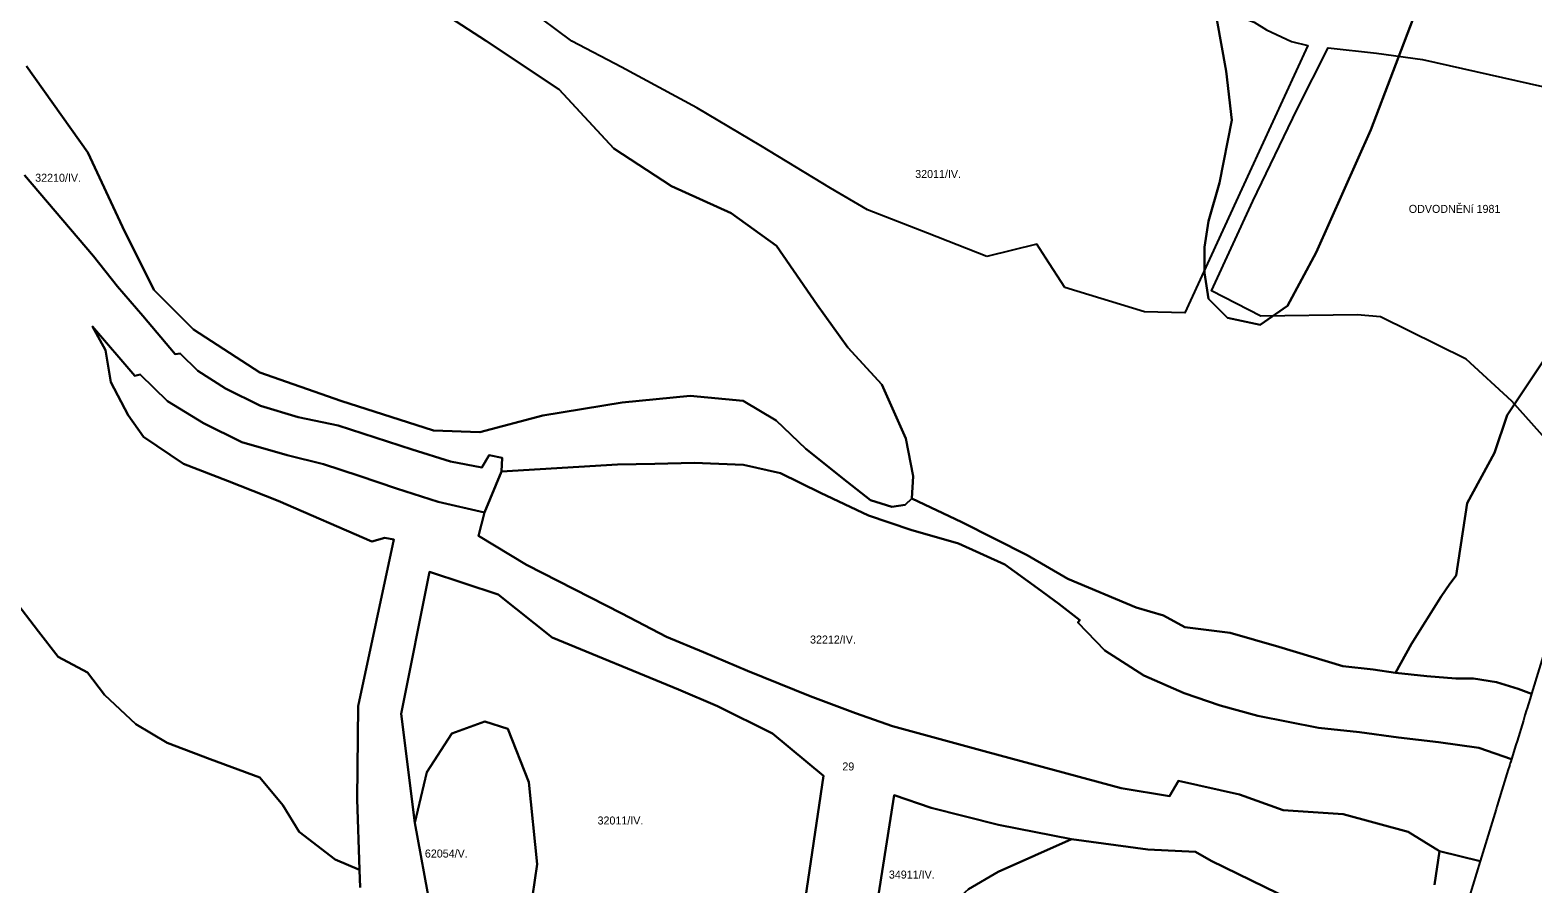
# Model space of a CAD drawing. Extents: x -521621 to -516761, y -1190184 to -1184927.
# Drawn here: x -518211 to -517460, y -1188092 to -1187665 of the extents above; entities that cross this region are included whole.
import ezdxf

# ---------------------------------------------------------------- set-up
doc = ezdxf.new("R2010")
doc.units = 0
doc.layers.add('BPEJ_s', color=7, linetype='Continuous')
doc.layers.add('odvodneni_s', color=7, linetype='Continuous')

msp = doc.modelspace()

# ---------------------------------------------------------------- linework, layer by layer
at = {"layer": 'BPEJ_s'}
for p, q in [((-518213.64, -1187737.85), (-518179.13, -1187778.41)), ((-518179.13, -1187778.41), (-518167.09, -1187793.48)), ((-518167.09, -1187793.48), (-518154.41, -1187808.16)), ((-518154.41, -1187808.16), (-518138.39, -1187827.34)), ((-518158.47, -1187838.17), (-518179.66, -1187813.57)), ((-518179.66, -1187813.57), (-518173.12, -1187825.31)), ((-518173.12, -1187825.31), (-518170.41, -1187841.33)), ((-518138.39, -1187827.34), (-518135.81, -1187827.06)), ((-518135.81, -1187827.06), (-518126.94, -1187835.65)), ((-518155.76, -1187837.49), (-518158.47, -1187838.17)), ((-518142.23, -1187850.8), (-518155.76, -1187837.49)), ((-518126.94, -1187835.65), (-518113.21, -1187844.53)), ((-518170.41, -1187841.33), (-518161.85, -1187857.8)), ((-518113.21, -1187844.53), (-518095.75, -1187853.12)), ((-518124.19, -1187861.86), (-518142.23, -1187850.8)), ((-518095.75, -1187853.12), (-518076.87, -1187858.85)), ((-518161.85, -1187857.8), (-518154.18, -1187868.63)), ((-518076.87, -1187858.85), (-518056.84, -1187863)), ((-518154.18, -1187868.63), (-518134.11, -1187882.17)), ((-518105.03, -1187871.34), (-518124.19, -1187861.86)), ((-518056.84, -1187863), (-518019.92, -1187875.03)), ((-518082.26, -1187877.88), (-518105.03, -1187871.34)), ((-518019.92, -1187875.03), (-518000.61, -1187881.04)), ((-518134.11, -1187882.17), (-518112.24, -1187890.75)), ((-518064.22, -1187882.4), (-518082.26, -1187877.88)), ((-518046.39, -1187888.2), (-518064.22, -1187882.4)), ((-518000.61, -1187881.04), (-517985.01, -1187884.05)), ((-517985.01, -1187884.05), (-517981.29, -1187877.89)), ((-517981.29, -1187877.89), (-517974.85, -1187879.18)), ((-517974.85, -1187879.18), (-517975.14, -1187886.06)), ((-518112.24, -1187890.75), (-518086.88, -1187900.67)), ((-518027.65, -1187894.51), (-518046.39, -1187888.2)), ((-517975.14, -1187886.06), (-517983.72, -1187906.53)), ((-518006.9, -1187901.24), (-518027.65, -1187894.51)), ((-518086.88, -1187900.67), (-518039.99, -1187921.04)), ((-517983.72, -1187906.53), (-518006.9, -1187901.24)), ((-518029.09, -1187919.95), (-518046.87, -1188003.31)), ((-518039.99, -1187921.04), (-518033.45, -1187919.22)), ((-518033.45, -1187919.22), (-518029.09, -1187919.95)), ((-518206.66, -1187966.08), (-518219.21, -1187949.69)), ((-518196.87, -1187978.64), (-518206.66, -1187966.08)), ((-518182.2, -1187986.52), (-518196.87, -1187978.64)), ((-518173.59, -1187997.71), (-518182.2, -1187986.52)), ((-518157.98, -1188012.41), (-518173.59, -1187997.71)), ((-518046.87, -1188003.31), (-518047.36, -1188049.86)), ((-518142.37, -1188021.59), (-518157.98, -1188012.41)), ((-518120.8, -1188029.86), (-518142.37, -1188021.59)), ((-518096.01, -1188039.05), (-518120.8, -1188029.86)), ((-518084.53, -1188052.83), (-518096.01, -1188039.05)), ((-518076.27, -1188066.15), (-518084.53, -1188052.83)), ((-518047.36, -1188049.86), (-518046.19, -1188085.08)), ((-518058.36, -1188079.93), (-518076.27, -1188066.15)), ((-518046.19, -1188085.08), (-518058.36, -1188079.93))]:
    msp.add_line(p, q, dxfattribs=at)
for points in [[(-517617.66, -1187660.01), (-517612.9, -1187685.91), (-517610.17, -1187710.45), (-517616.3, -1187741.8), (-517621.75, -1187760.89), (-517623.8, -1187773.84), (-517623.8, -1187786.79), (-517621.75, -1187799.74), (-517612.22, -1187809.28), (-517595.87, -1187812.69), (-517582.24, -1187803.15), (-517567.94, -1187776.56), (-517540.69, -1187715.22), (-517518.21, -1187656.6)], [(-517518.21, -1187656.6), (-517540.69, -1187715.22), (-517567.94, -1187776.56), (-517582.24, -1187803.15), (-517595.87, -1187812.69), (-517612.22, -1187809.28), (-517621.75, -1187799.74), (-517623.8, -1187786.79), (-517623.8, -1187773.84), (-517621.75, -1187760.89), (-517616.3, -1187741.8), (-517610.17, -1187710.45), (-517612.9, -1187685.91), (-517617.66, -1187660.01)], [(-518000.68, -1187659.17), (-517983.27, -1187670.54), (-517946.33, -1187695.06), (-517918.98, -1187724.56), (-517890.21, -1187743.4), (-517860.37, -1187756.91), (-517837.64, -1187773.26), (-517817.39, -1187802.76), (-517802.11, -1187824.08), (-517785.06, -1187842.57), (-517772.99, -1187869.58), (-517769.43, -1187888.42), (-517770.12, -1187899.48), (-517773.34, -1187902.63), (-517780.01, -1187903.61), (-517790.77, -1187900.3), (-517802.35, -1187891.19), (-517823.03, -1187874.64), (-517837.92, -1187860.57), (-517854.46, -1187850.63), (-517880.93, -1187848.15), (-517914.85, -1187851.46), (-517954.55, -1187858.08), (-517985.99, -1187866.36), (-518009.15, -1187865.53), (-518055.47, -1187850.63), (-518096.01, -1187836.56), (-518129.09, -1187815.04), (-518148.95, -1187795.18), (-518164.66, -1187763.72), (-518182.04, -1187726.48), (-518212.64, -1187683.44)], [(-517448.42, -1187821.9), (-517472.41, -1187857.91), (-517478.78, -1187876.76), (-517492.39, -1187901.92), (-517498, -1187937.94), (-517501.04, -1187942.11), (-517505.43, -1187948.44), (-517520.28, -1187972.09), (-517528.25, -1187986.67), (-517539.52, -1187985.02), (-517554.63, -1187983.37), (-517586.52, -1187973.74), (-517610.98, -1187966.59), (-517633.52, -1187963.84), (-517644.24, -1187958.06), (-517657.98, -1187953.94), (-517692.06, -1187939.64), (-517712.4, -1187927.81), (-517745.11, -1187911.31), (-517770.12, -1187899.48), (-517769.43, -1187888.42), (-517772.99, -1187869.58), (-517785.06, -1187842.57), (-517802.11, -1187824.08), (-517817.39, -1187802.76), (-517837.64, -1187773.26), (-517860.37, -1187756.91), (-517890.21, -1187743.4), (-517918.98, -1187724.56), (-517946.33, -1187695.06), (-517983.27, -1187670.54), (-518000.68, -1187659.17)], [(-518212.64, -1187683.44), (-518182.04, -1187726.48), (-518164.66, -1187763.72), (-518148.95, -1187795.18), (-518129.09, -1187815.04), (-518096.01, -1187836.56), (-518055.47, -1187850.63), (-518009.15, -1187865.53), (-517985.99, -1187866.36), (-517954.55, -1187858.08), (-517914.85, -1187851.46), (-517880.93, -1187848.15), (-517854.46, -1187850.63), (-517837.92, -1187860.57), (-517823.03, -1187874.64), (-517802.35, -1187891.19), (-517790.77, -1187900.3), (-517780.01, -1187903.61), (-517773.34, -1187902.63), (-517770.12, -1187899.48), (-517745.11, -1187911.31), (-517712.4, -1187927.81), (-517692.06, -1187939.64), (-517657.98, -1187953.94), (-517644.24, -1187958.06), (-517633.52, -1187963.84), (-517610.98, -1187966.59), (-517586.52, -1187973.74), (-517554.63, -1187983.37), (-517539.52, -1187985.02), (-517528.25, -1187986.67), (-517512.58, -1187988.32), (-517498.14, -1187989.48), (-517489.25, -1187989.48), (-517477.76, -1187991.33), (-517467.02, -1187994.67), (-517460.27, -1187997.18), (-517460.97, -1187999.46), (-517462.6, -1188004.76), (-517462.68, -1188004.99), (-517462.75, -1188005.22), (-517463.55, -1188007.83), (-517464.35, -1188010.44), (-517467.53, -1188020.76), (-517468.1, -1188022.61), (-517470.32, -1188029.84), (-517486.54, -1188024.11), (-517506.82, -1188021.25), (-517526.82, -1188018.96), (-517546.24, -1188016.39), (-517566.8, -1188014.1), (-517597.08, -1188008.1), (-517615.93, -1188002.96), (-517633.93, -1187996.84), (-517654.1, -1187988.05), (-517673.55, -1187975.47), (-517687.08, -1187961.46), (-517686.13, -1187960.27), (-517696.57, -1187952.2), (-517707.24, -1187944.36), (-517723.51, -1187932.46), (-517746.77, -1187921.95), (-517770.52, -1187915.2), (-517791.77, -1187907.94), (-517815.77, -1187896.68), (-517835.78, -1187886.92), (-517854.28, -1187882.67), (-517878.94, -1187881.73), (-517898.5, -1187882.27), (-517917.15, -1187882.45), (-517975.14, -1187886.06), (-517974.85, -1187879.18), (-517981.29, -1187877.89), (-517985.01, -1187884.05), (-518000.61, -1187881.04), (-518019.92, -1187875.03), (-518056.84, -1187863), (-518076.87, -1187858.85), (-518095.75, -1187853.12), (-518113.21, -1187844.53), (-518126.94, -1187835.65), (-518135.81, -1187827.06), (-518138.39, -1187827.34), (-518154.41, -1187808.16), (-518167.09, -1187793.48), (-518179.13, -1187778.41), (-518213.64, -1187737.85)], [(-518045.9, -1188093.97), (-518046.19, -1188085.08), (-518047.36, -1188049.86), (-518046.87, -1188003.31), (-518029.09, -1187919.95), (-518033.45, -1187919.22), (-518039.99, -1187921.04), (-518086.88, -1187900.67), (-518112.24, -1187890.75), (-518134.11, -1187882.17), (-518154.18, -1187868.63), (-518161.85, -1187857.8), (-518170.41, -1187841.33), (-518173.12, -1187825.31), (-518179.66, -1187813.57), (-518158.47, -1187838.17), (-518155.76, -1187837.49), (-518142.23, -1187850.8), (-518124.19, -1187861.86), (-518105.03, -1187871.34), (-518082.26, -1187877.88), (-518064.22, -1187882.4), (-518046.39, -1187888.2), (-518027.65, -1187894.51), (-518006.9, -1187901.24), (-517983.72, -1187906.53), (-517986.73, -1187918.13), (-517962.73, -1187932.64), (-517915.07, -1187957.04), (-517892.64, -1187968.68), (-517874.24, -1187976.3), (-517852.24, -1187985.62), (-517820.93, -1187998.32), (-517798.3, -1188006.79), (-517779.68, -1188013.35), (-517732.15, -1188026.28), (-517665.49, -1188044.33), (-517641.29, -1188048.36), (-517636.78, -1188040.69), (-517606.22, -1188047.55), (-517584.51, -1188055.27), (-517554.52, -1188057.27), (-517521.96, -1188066.13), (-517506.25, -1188075.85), (-517508.82, -1188092.71)], [(-517444.26, -1187945), (-517460.27, -1187997.18), (-517467.02, -1187994.67), (-517477.76, -1187991.33), (-517489.25, -1187989.48), (-517498.14, -1187989.48), (-517512.58, -1187988.32), (-517528.25, -1187986.67), (-517520.28, -1187972.09), (-517505.43, -1187948.44), (-517501.04, -1187942.11), (-517498, -1187937.94), (-517492.39, -1187901.92), (-517478.78, -1187876.76), (-517472.41, -1187857.91), (-517448.42, -1187821.9)], [(-517960.81, -1188106.35), (-517957.37, -1188082.23), (-517961.5, -1188041.34), (-517972.06, -1188014.7), (-517983.54, -1188011.03), (-518000.06, -1188017), (-518012.46, -1188036.29), (-518018.47, -1188061.62), (-518025.33, -1188007.23), (-518011.13, -1187936.17), (-517976.85, -1187947.44), (-517949.92, -1187969), (-517886.76, -1187994.97), (-517867.17, -1188003.31), (-517839.75, -1188017.03), (-517814.29, -1188038.1), (-517833.89, -1188171.06)], [(-517833.89, -1188171.06), (-517814.29, -1188038.1), (-517839.75, -1188017.03), (-517867.17, -1188003.31), (-517886.76, -1187994.97), (-517949.92, -1187969), (-517976.85, -1187947.44), (-518011.13, -1187936.17), (-518025.33, -1188007.23), (-518018.47, -1188061.62), (-518002.81, -1188146.9)], [(-518219.21, -1187949.69), (-518206.66, -1187966.08), (-518196.87, -1187978.64), (-518182.2, -1187986.52), (-518173.59, -1187997.71), (-518157.98, -1188012.41), (-518142.37, -1188021.59), (-518120.8, -1188029.86), (-518096.01, -1188039.05), (-518084.53, -1188052.83), (-518076.27, -1188066.15), (-518058.36, -1188079.93), (-518046.19, -1188085.08), (-518045.9, -1188093.97)], [(-517580.51, -1188100.15), (-517620.48, -1188080.59), (-517628.22, -1188076.12), (-517652.05, -1188074.93), (-517690.18, -1188069.86), (-517726.82, -1188062.71), (-517760.33, -1188054.17), (-517778.93, -1188047.85), (-517795.95, -1188155.97)], [(-517741.81, -1188094.89), (-517726.97, -1188086.09), (-517690.18, -1188069.86), (-517652.05, -1188074.93), (-517628.22, -1188076.12), (-517620.48, -1188080.59), (-517580.51, -1188100.15)], [(-517508.82, -1188092.71), (-517506.25, -1188075.85), (-517485.94, -1188080.73), (-517500.67, -1188128.84)]]:
    msp.add_lwpolyline(points, dxfattribs=at)
for points in [[(-517983.72, -1187906.53), (-517975.14, -1187886.06), (-517917.15, -1187882.45), (-517898.5, -1187882.27), (-517878.94, -1187881.73), (-517854.28, -1187882.67), (-517835.78, -1187886.92), (-517815.77, -1187896.68), (-517791.77, -1187907.94), (-517770.52, -1187915.2), (-517746.77, -1187921.95), (-517723.51, -1187932.46), (-517707.24, -1187944.36), (-517696.57, -1187952.2), (-517686.13, -1187960.27), (-517687.08, -1187961.46), (-517673.55, -1187975.47), (-517654.1, -1187988.05), (-517633.93, -1187996.84), (-517615.93, -1188002.96), (-517597.08, -1188008.1), (-517566.8, -1188014.1), (-517546.24, -1188016.39), (-517526.82, -1188018.96), (-517506.82, -1188021.25), (-517486.54, -1188024.11), (-517470.32, -1188029.84), (-517470.7, -1188031.07), (-517470.92, -1188031.77), (-517471.13, -1188032.47), (-517471.52, -1188033.71), (-517471.9, -1188034.95), (-517474.43, -1188043.17), (-517476.96, -1188051.38), (-517477.28, -1188052.43), (-517477.6, -1188053.48), (-517477.81, -1188054.16), (-517478.02, -1188054.84), (-517485.94, -1188080.73), (-517506.25, -1188075.85), (-517521.96, -1188066.13), (-517554.52, -1188057.27), (-517584.51, -1188055.27), (-517606.22, -1188047.55), (-517636.78, -1188040.69), (-517641.29, -1188048.36), (-517665.49, -1188044.33), (-517732.15, -1188026.28), (-517779.68, -1188013.35), (-517798.3, -1188006.79), (-517820.93, -1187998.32), (-517852.24, -1187985.62), (-517874.24, -1187976.3), (-517892.64, -1187968.68), (-517915.07, -1187957.04), (-517962.73, -1187932.64), (-517986.73, -1187918.13)], [(-518018.47, -1188061.62), (-518012.46, -1188036.29), (-518000.06, -1188017), (-517983.54, -1188011.03), (-517972.06, -1188014.7), (-517961.5, -1188041.34), (-517957.37, -1188082.23), (-517960.81, -1188106.35), (-517961.5, -1188111.16), (-517967.47, -1188132.29), (-517977.11, -1188146.99), (-517984.45, -1188150.67), (-517994.55, -1188151.13), (-518000.98, -1188147.91), (-518002.81, -1188146.9)], [(-517795.95, -1188155.97), (-517778.93, -1188047.85), (-517760.33, -1188054.17), (-517726.82, -1188062.71), (-517690.18, -1188069.86), (-517726.97, -1188086.09), (-517741.81, -1188094.89), (-517747.31, -1188099.84), (-517769.3, -1188122.39), (-517781.39, -1188140.55)]]:
    msp.add_lwpolyline(points, close=True, dxfattribs=at)
at = {"layer": 'odvodneni_s'}
for points in [[(-517940, -1187670.92), (-517962.84, -1187653.94)], [(-517620.95, -1187653.19), (-517598.93, -1187661.48), (-517592.76, -1187665.26), (-517580.33, -1187671.15), (-517572.04, -1187673.09), (-517601.22, -1187736.39), (-517633.65, -1187806.72), (-517653.69, -1187806.18), (-517693.66, -1187793.99)], [(-517915.16, -1187683.88), (-517940, -1187670.92)], [(-517449.06, -1187874.4), (-517470.2, -1187850.94), (-517492.89, -1187829.8), (-517535.79, -1187808.65), (-517547.52, -1187807.73), (-517595.67, -1187808.34), (-517620.19, -1187795.76), (-517599.53, -1187750.9), (-517577.46, -1187704.91), (-517562.02, -1187674.2), (-517537.86, -1187676.87), (-517514.84, -1187680), (-517454.78, -1187693.54)], [(-517877.58, -1187704.18), (-517915.16, -1187683.88)], [(-517845.56, -1187723.31), (-517877.58, -1187704.18)], [(-517810.68, -1187744.45), (-517845.56, -1187723.31)], [(-517792.16, -1187755.26), (-517810.68, -1187744.45)], [(-517762.3, -1187766.83), (-517792.16, -1187755.26)], [(-517732.59, -1187778.56), (-517762.3, -1187766.83)], [(-517707.51, -1187772.39), (-517732.59, -1187778.56)], [(-517703.05, -1187779.35), (-517707.51, -1187772.39)], [(-517693.66, -1187793.99), (-517703.05, -1187779.35)]]:
    msp.add_lwpolyline(points, dxfattribs=at)

# ---------------------------------------------------------------- texts
at = {"layer": 'BPEJ_s'}
for s, p in [('32210/IV.', (-518208.3, -1187741.19)), ('32011/IV.', (-517768.39, -1187739.31)), ('32212/IV.', (-517820.94, -1187972.02)), ('29', (-517804.8, -1188035.46)), ('32011/IV.', (-517927.17, -1188062.48)), ('62054/V.', (-518013.49, -1188079)), ('34911/IV.', (-517781.53, -1188089.51))]:
    msp.add_text(s, height=4, dxfattribs=at).set_placement(p)
at = {"layer": 'odvodneni_s'}
msp.add_text('ODVODNĚNí 1981', height=4, dxfattribs=at).set_placement((-517521.63, -1187756.75))

doc.saveas('drawing.dxf')
